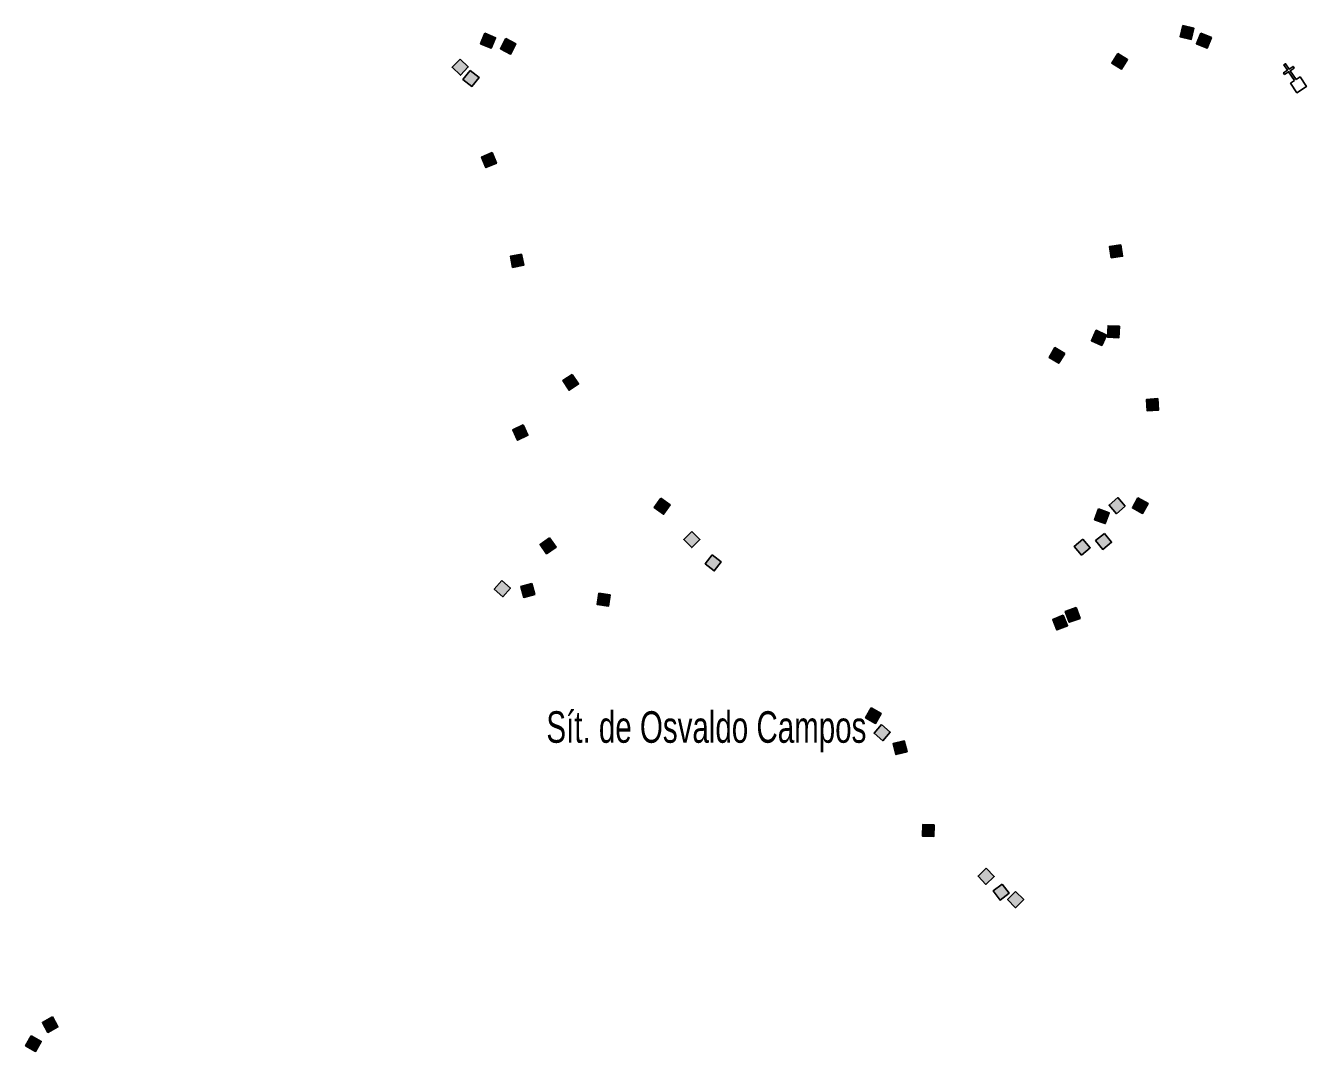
# Model space of a CAD drawing. Extents: x 679 to 705, y 7427.4 to 7455.4.
# Drawn here: x 693.036 to 696.285, y 7443.973 to 7446.575 of the extents above; entities that cross this region are included whole.
import ezdxf

# ---------------------------------------------------------------- set-up
doc = ezdxf.new("R2010")
doc.units = 0
doc.header["$LTSCALE"] = 0.032
doc.layers.add('2', color=7, linetype='Continuous', lineweight=25)
doc.layers.add('6', color=7, linetype='Continuous', lineweight=25)
doc.layers.add('61', color=7, linetype='Continuous')

msp = doc.modelspace()

# ---------------------------------------------------------------- hatches: boundary and pattern name
at = {"layer": '2'}
for points in [[(695.9714, 7446.5755), (695.9995, 7446.5686), (695.9927, 7446.5404), (695.9645, 7446.5473)], [(694.2013, 7446.5562), (694.2281, 7446.5449), (694.2168, 7446.5182), (694.1901, 7446.5294)], [(694.2539, 7446.5424), (694.2796, 7446.5289), (694.2661, 7446.5032), (694.2404, 7446.5167)], [(696.017, 7446.5561), (696.0438, 7446.545), (696.0327, 7446.5182), (696.0059, 7446.5294)], [(694.138, 7446.4907), (694.159, 7446.4707), (694.139, 7446.4497), (694.118, 7446.4697)], [(695.8064, 7446.5045), (695.831, 7446.4892), (695.8157, 7446.4646), (695.7911, 7446.4799)], [(694.1633, 7446.4618), (694.1861, 7446.4439), (694.1682, 7446.4211), (694.1454, 7446.439)], [(694.2192, 7446.2532), (694.2304, 7446.2264), (694.2036, 7446.2153), (694.1925, 7446.2421)], [(695.8142, 7446.0192), (695.8183, 7445.9905), (695.7896, 7445.9864), (695.7855, 7446.0151)], [(694.2943, 7445.9958), (694.2998, 7445.9673), (694.2713, 7445.9619), (694.2658, 7445.9903)], [(695.7778, 7445.7904), (695.7658, 7445.764), (695.7394, 7445.7761), (695.7515, 7445.8025)], [(695.8105, 7445.8126), (695.8093, 7445.7836), (695.7803, 7445.7849), (695.7816, 7445.8139)], [(695.6717, 7445.7436), (695.6567, 7445.7188), (695.6319, 7445.7338), (695.6469, 7445.7586)], [(694.4228, 7445.6907), (694.4388, 7445.6665), (694.4146, 7445.6505), (694.3986, 7445.6747)], [(695.9077, 7445.6291), (695.9099, 7445.6002), (695.881, 7445.598), (695.8788, 7445.6269)], [(694.2978, 7445.5624), (694.3103, 7445.5362), (694.2841, 7445.5237), (694.2717, 7445.5499)], [(694.6477, 7445.3763), (694.6713, 7445.3594), (694.6544, 7445.3358), (694.6308, 7445.3527)], [(695.8252, 7445.356), (695.8032, 7445.3371), (695.7843, 7445.3591), (695.8063, 7445.378)], [(695.8575, 7445.3773), (695.883, 7445.3634), (695.8691, 7445.3379), (695.8436, 7445.3518)], [(695.7577, 7445.3492), (695.7848, 7445.339), (695.7747, 7445.3119), (695.7475, 7445.322)], [(694.365, 7445.2758), (694.3814, 7445.2519), (694.3575, 7445.2355), (694.3411, 7445.2594)], [(694.7258, 7445.292), (694.7463, 7445.2715), (694.7258, 7445.251), (694.7053, 7445.2715)], [(695.718, 7445.2728), (695.7366, 7445.2506), (695.7143, 7445.232), (695.6957, 7445.2542)], [(695.7725, 7445.2871), (695.7907, 7445.2646), (695.7682, 7445.2464), (695.75, 7445.2689)], [(694.7777, 7445.2328), (694.8005, 7445.2149), (694.7827, 7445.1921), (694.7598, 7445.21)], [(694.2437, 7445.1675), (694.2656, 7445.1484), (694.2466, 7445.1266), (694.2247, 7445.1456)], [(694.3201, 7445.1604), (694.3277, 7445.1324), (694.2997, 7445.1248), (694.2921, 7445.1527)], [(694.519, 7445.1313), (694.5149, 7445.1026), (694.4862, 7445.1067), (694.4903, 7445.1354)], [(695.6681, 7445.08), (695.6789, 7445.0531), (695.652, 7445.0422), (695.6412, 7445.0691)], [(695.7004, 7445.0989), (695.7105, 7445.0717), (695.6834, 7445.0616), (695.6732, 7445.0888)], [(695.1811, 7444.8445), (695.2063, 7444.8302), (695.192, 7444.805), (695.1668, 7444.8193)], [(695.2071, 7444.8021), (695.2291, 7444.7832), (695.2102, 7444.7612), (695.1882, 7444.7801)], [(695.2648, 7444.7613), (695.2719, 7444.7332), (695.2437, 7444.7261), (695.2367, 7444.7543)], [(695.3408, 7444.5474), (695.3398, 7444.5184), (695.3109, 7444.5194), (695.3118, 7444.5483)], [(695.4728, 7444.4377), (695.4929, 7444.4168), (695.4719, 7444.3967), (695.4519, 7444.4176)], [(695.5134, 7444.3976), (695.5308, 7444.3744), (695.5076, 7444.357), (695.4902, 7444.3803)], [(695.5473, 7444.3787), (695.5678, 7444.3581), (695.5473, 7444.3376), (695.5268, 7444.3582)], [(693.1039, 7444.0605), (693.118, 7444.0352), (693.0927, 7444.021), (693.0786, 7444.0464)], [(693.0504, 7444.0125), (693.0756, 7443.9982), (693.0613, 7443.973), (693.0361, 7443.9873)]]:
    msp.add_hatch(color=256, dxfattribs=at).paths.add_polyline_path(points)

# ---------------------------------------------------------------- linework, layer by layer
for points in [[(695.9714, 7446.5755), (695.9995, 7446.5686), (695.9927, 7446.5404), (695.9645, 7446.5473)], [(694.2013, 7446.5562), (694.2281, 7446.5449), (694.2168, 7446.5182), (694.1901, 7446.5294)], [(694.2539, 7446.5424), (694.2796, 7446.5289), (694.2661, 7446.5032), (694.2404, 7446.5167)], [(696.017, 7446.5561), (696.0438, 7446.545), (696.0327, 7446.5182), (696.0059, 7446.5294)], [(694.138, 7446.4907), (694.159, 7446.4707), (694.139, 7446.4497), (694.118, 7446.4697)], [(695.8064, 7446.5045), (695.831, 7446.4892), (695.8157, 7446.4646), (695.7911, 7446.4799)], [(694.1633, 7446.4618), (694.1861, 7446.4439), (694.1682, 7446.4211), (694.1454, 7446.439)], [(694.2192, 7446.2532), (694.2304, 7446.2264), (694.2036, 7446.2153), (694.1925, 7446.2421)], [(695.8142, 7446.0192), (695.8183, 7445.9905), (695.7896, 7445.9864), (695.7855, 7446.0151)], [(694.2943, 7445.9958), (694.2998, 7445.9673), (694.2713, 7445.9619), (694.2658, 7445.9903)], [(695.7778, 7445.7904), (695.7658, 7445.764), (695.7394, 7445.7761), (695.7515, 7445.8025)], [(695.8105, 7445.8126), (695.8093, 7445.7836), (695.7803, 7445.7849), (695.7816, 7445.8139)], [(695.6717, 7445.7436), (695.6567, 7445.7188), (695.6319, 7445.7338), (695.6469, 7445.7586)], [(694.4228, 7445.6907), (694.4388, 7445.6665), (694.4146, 7445.6505), (694.3986, 7445.6747)], [(695.9077, 7445.6291), (695.9099, 7445.6002), (695.881, 7445.598), (695.8788, 7445.6269)], [(694.2978, 7445.5624), (694.3103, 7445.5362), (694.2841, 7445.5237), (694.2717, 7445.5499)], [(694.6477, 7445.3763), (694.6713, 7445.3594), (694.6544, 7445.3358), (694.6308, 7445.3527)], [(695.8252, 7445.356), (695.8032, 7445.3371), (695.7843, 7445.3591), (695.8063, 7445.378)], [(695.8575, 7445.3773), (695.883, 7445.3634), (695.8691, 7445.3379), (695.8436, 7445.3518)], [(695.7577, 7445.3492), (695.7848, 7445.339), (695.7747, 7445.3119), (695.7475, 7445.322)], [(694.365, 7445.2758), (694.3814, 7445.2519), (694.3575, 7445.2355), (694.3411, 7445.2594)], [(694.7258, 7445.292), (694.7463, 7445.2715), (694.7258, 7445.251), (694.7053, 7445.2715)], [(695.718, 7445.2728), (695.7366, 7445.2506), (695.7143, 7445.232), (695.6957, 7445.2542)], [(695.7725, 7445.2871), (695.7907, 7445.2646), (695.7682, 7445.2464), (695.75, 7445.2689)], [(694.7777, 7445.2328), (694.8005, 7445.2149), (694.7827, 7445.1921), (694.7598, 7445.21)], [(694.2437, 7445.1675), (694.2656, 7445.1484), (694.2466, 7445.1266), (694.2247, 7445.1456)], [(694.3201, 7445.1604), (694.3277, 7445.1324), (694.2997, 7445.1248), (694.2921, 7445.1527)], [(694.519, 7445.1313), (694.5149, 7445.1026), (694.4862, 7445.1067), (694.4903, 7445.1354)], [(695.6681, 7445.08), (695.6789, 7445.0531), (695.652, 7445.0422), (695.6412, 7445.0691)], [(695.7004, 7445.0989), (695.7105, 7445.0717), (695.6834, 7445.0616), (695.6732, 7445.0888)], [(695.1811, 7444.8445), (695.2063, 7444.8302), (695.192, 7444.805), (695.1668, 7444.8193)], [(695.2071, 7444.8021), (695.2291, 7444.7832), (695.2102, 7444.7612), (695.1882, 7444.7801)], [(695.2648, 7444.7613), (695.2719, 7444.7332), (695.2437, 7444.7261), (695.2367, 7444.7543)], [(695.3408, 7444.5474), (695.3398, 7444.5184), (695.3109, 7444.5194), (695.3118, 7444.5483)], [(695.4728, 7444.4377), (695.4929, 7444.4168), (695.4719, 7444.3967), (695.4519, 7444.4176)], [(695.5134, 7444.3976), (695.5308, 7444.3744), (695.5076, 7444.357), (695.4902, 7444.3803)], [(695.5473, 7444.3787), (695.5678, 7444.3581), (695.5473, 7444.3376), (695.5268, 7444.3582)], [(693.1039, 7444.0605), (693.118, 7444.0352), (693.0927, 7444.021), (693.0786, 7444.0464)], [(693.0504, 7444.0125), (693.0756, 7443.9982), (693.0613, 7443.973), (693.0361, 7443.9873)]]:
    msp.add_lwpolyline(points, close=True, dxfattribs=at)
at = {"layer": '6'}
for points in [[(696.2546, 7446.4359), (696.2396, 7446.4585), (696.2295, 7446.4518), (696.2268, 7446.4559), (696.2369, 7446.4626), (696.2279, 7446.4763), (696.2319, 7446.4789), (696.2409, 7446.4652), (696.251, 7446.4719), (696.2537, 7446.4678), (696.2436, 7446.4611), (696.2586, 7446.4385)], [(696.2586, 7446.4385), (696.2687, 7446.4452), (696.2847, 7446.421), (696.2605, 7446.405), (696.2445, 7446.4292), (696.2546, 7446.4359)]]:
    msp.add_lwpolyline(points, dxfattribs=at)

# ---------------------------------------------------------------- texts
at = {"layer": '61', "width": 0.7}
msp.add_text('Sít. de Osvaldo Campos', height=0.08, dxfattribs=at).set_placement((694.357, 7444.756))

doc.saveas('drawing.dxf')
